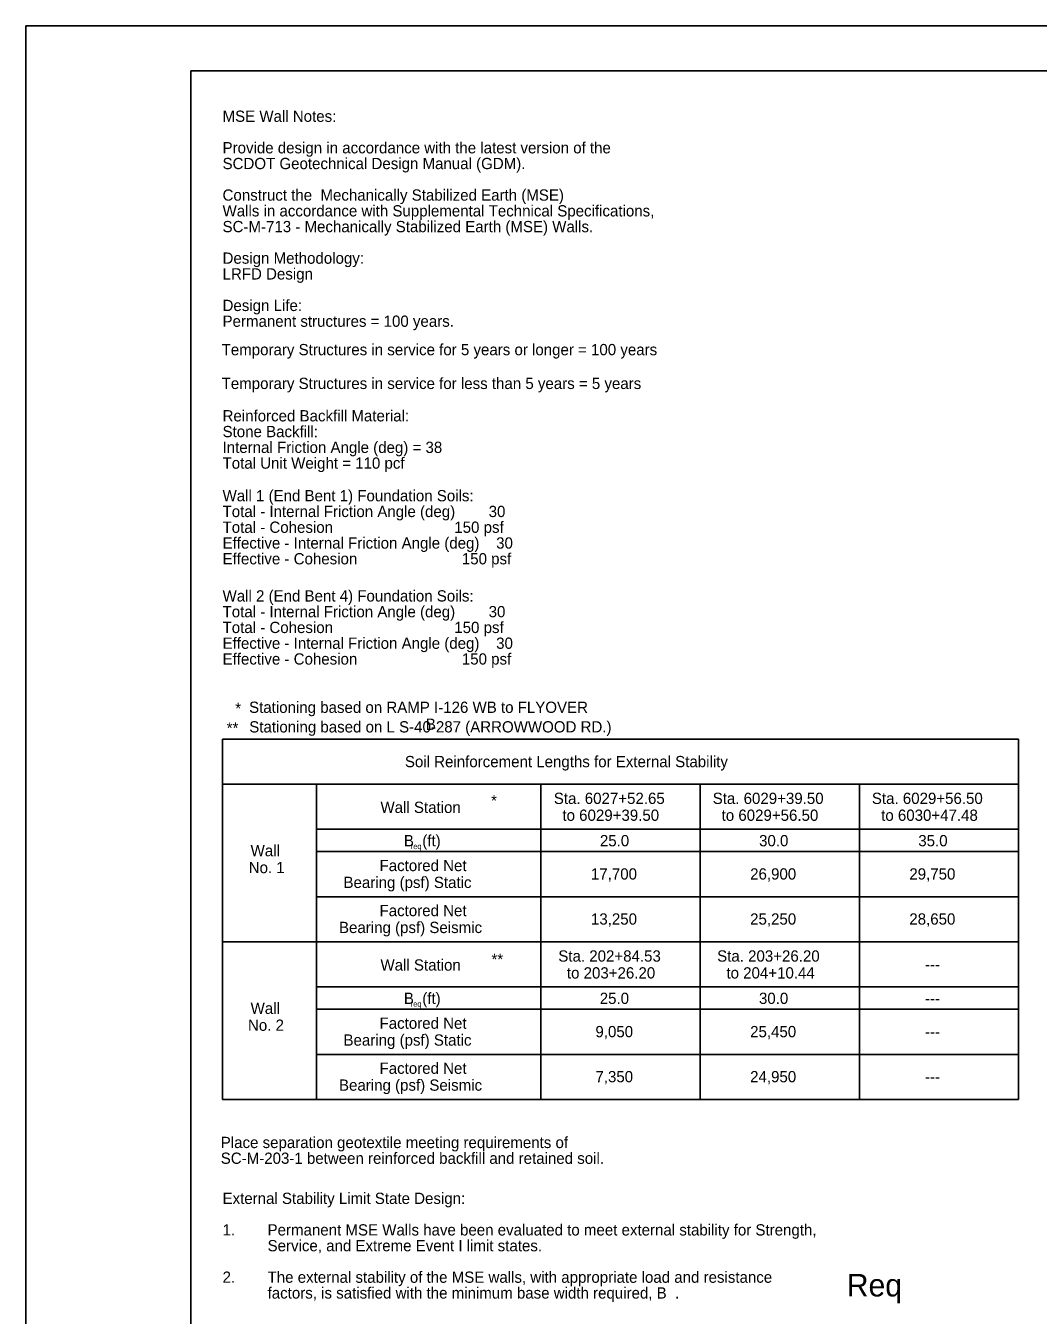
# Model space of a CAD drawing. Extents: x 96 to 240, y 601 to 689.
# Drawn here: x 95.8 to 140.8, y 631.8 to 689 of the extents above; entities that cross this region are included whole.
import ezdxf

# ---------------------------------------------------------------- set-up
doc = ezdxf.new("R2010")
doc.units = 0
for name, color, linetype in [('BR_BORDER LINES', 7, 'Continuous'), ('BR_TABLE LINES', 7, 'Continuous'), ('BR_TEXT', 7, 'Continuous'), ('Level 31', 7, 'Continuous')]:
    doc.layers.add(name, color=color, linetype=linetype)

msp = doc.modelspace()

# ---------------------------------------------------------------- linework, layer by layer
at = {"layer": 'BR_BORDER LINES'}
for p in [(237.837, 687.003), (103.173, 603.003)]:
    msp.add_line(p, (103.173, 687.003), dxfattribs=at)
at = {"layer": 'BR_TABLE LINES'}
for p, q in [((139.93, 657.337), (104.579, 657.337)), ((104.579, 657.337), (104.579, 641.337)), ((139.93, 657.337), (139.93, 641.337)), ((139.93, 655.337), (104.579, 655.337)), ((108.755, 655.337), (108.755, 641.337)), ((118.72, 655.337), (118.72, 641.337)), ((125.79, 655.337), (125.79, 641.337)), ((132.86, 655.337), (132.86, 641.337)), ((139.93, 653.337), (108.755, 653.337)), ((139.93, 652.337), (108.755, 652.337)), ((139.93, 650.337), (108.755, 650.337)), ((139.93, 648.337), (104.579, 648.337)), ((139.93, 646.337), (108.755, 646.337)), ((139.93, 645.337), (108.755, 645.337)), ((139.93, 643.337), (108.755, 643.337)), ((139.93, 641.337), (104.579, 641.337))]:
    msp.add_line(p, q, dxfattribs=at)
at = {"layer": 'Level 31'}
msp.add_line((239.84, 689.004), (95.84, 689.004), dxfattribs=at)
msp.add_lwpolyline([(95.84, 689.004), (95.84, 601.004), (239.84, 601.004), (239.84, 689.004)], dxfattribs=at)

# ---------------------------------------------------------------- texts
at = {"layer": 'BR_TEXT'}
for s, height, p in [('MSE Wall Notes:', 0.5, (104.579, 684.739)), ('Provide design in accordance with the latest version of the ', 0.5, (104.579, 683.339)), ('SCDOT Geotechnical Design Manual (GDM). ', 0.5, (104.579, 682.639)), ('Construct the  Mechanically Stabilized Earth (MSE) ', 0.5, (104.579, 681.239)), ('Walls in accordance with Supplemental Technical Specifications,', 0.5, (104.579, 680.539)), ('SC-M-713 - Mechanically Stabilized Earth (MSE) Walls.', 0.5, (104.579, 679.839)), ('Design Methodology:', 0.5, (104.579, 678.439)), ('LRFD Design', 0.5, (104.579, 677.739)), ('Design Life:', 0.5, (104.579, 676.339)), ('Permanent structures = 100 years.', 0.5, (104.579, 675.639)), ('Temporary Structures in service for 5 years or longer = 100 years ', 0.5, (104.538, 674.377)), ('Temporary Structures in service for less than 5 years = 5 years ', 0.5, (104.538, 672.877)), ('Reinforced Backfill Material:', 0.5, (104.579, 671.439)), ('Stone Backfill:', 0.5, (104.579, 670.739)), ('Internal Friction Angle (deg) = 38', 0.5, (104.579, 670.039)), ('Total Unit Weight = 110 pcf', 0.5, (104.579, 669.339)), ('Wall 1 (End Bent 1) Foundation Soils:', 0.5, (104.579, 667.892)), ('Total - Internal Friction Angle (deg)        30', 0.5, (104.579, 667.192)), ('Total - Cohesion                             150 psf', 0.5, (104.579, 666.492)), ('Effective - Internal Friction Angle (deg)    30', 0.5, (104.579, 665.792)), ('Effective - Cohesion                         150 psf', 0.5, (104.579, 665.092)), ('Wall 2 (End Bent 4) Foundation Soils:', 0.5, (104.579, 663.443)), ('Total - Internal Friction Angle (deg)        30', 0.5, (104.579, 662.743)), ('Total - Cohesion                             150 psf', 0.5, (104.579, 662.043)), ('Effective - Internal Friction Angle (deg)    30', 0.5, (104.579, 661.343)), ('Effective - Cohesion                         150 psf', 0.5, (104.579, 660.643)), ('Stationing based on RAMP I-126 WB to FLYOVER', 0.5, (105.757, 658.498)), ('Stationing based on L S-40-287 (ARROWWOOD RD.)', 0.5, (105.764, 657.629)), ('B', 0.5, (113.607, 657.745)), ('Place separation geotextile meeting requirements of ', 0.5, (104.499, 639.177)), ('SC-M-203-1 between reinforced backfill and retained soil.', 0.5, (104.499, 638.477)), ('External Stability Limit State Design:', 0.5, (104.579, 636.696)), ('1.', 0.5, (104.579, 635.296)), ('Permanent MSE Walls have been evaluated to meet external stability for Strength,', 0.5, (106.579, 635.296)), ('Service, and Extreme Event I limit states.', 0.5, (106.579, 634.596)), ('2.', 0.5, (104.579, 633.196)), ('The external stability of the MSE walls, with appropriate load and resistance', 0.5, (106.579, 633.196)), ('          Req', 1, (128.587, 632.59)), ('factors, is satisfied with the minimum base width required, B  .', 0.5, (106.579, 632.496))]:
    msp.add_text(s, height=height, dxfattribs=at).set_placement(p)
for s, height, p in [('*', 0.5, (105.143, 658.445)), ('**', 0.5, (104.764, 657.577)), ('Soil Reinforcement Lengths for External Stability', 0.5, (112.677, 656.087)), ('Sta. 6027+52.65 ', 0.5, (119.291, 654.455)), ('Sta. 6029+39.50', 0.5, (126.346, 654.455)), ('Sta. 6029+56.50', 0.5, (133.416, 654.455)), ('Wall Station', 0.5, (111.592, 654.056)), ('*', 0.5, (116.504, 654.355)), ('to 6029+39.50', 0.5, (119.673, 653.705)), ('to 6029+56.50', 0.5, (126.743, 653.705)), ('to 6030+47.48', 0.5, (133.829, 653.705)), ('Wall', 0.5, (105.824, 652.134)), ('B  (ft)', 0.5, (112.631, 652.576)), ('req', 0.25, (112.933, 652.45)), ('25.0', 0.5, (121.337, 652.576)), ('30.0', 0.5, (128.407, 652.576)), ('35.0', 0.5, (135.477, 652.576)), ('No. 1', 0.5, (105.741, 651.384)), ('Factored Net', 0.5, (111.551, 651.473)), ('17,700', 0.5, (120.94, 651.098)), ('26,900', 0.5, (128.01, 651.098)), ('29,750', 0.5, (135.08, 651.098)), ('Bearing (psf) Static', 0.5, (109.95, 650.723)), ('Factored Net', 0.5, (111.551, 649.473)), ('Bearing (psf) Seismic', 0.5, (109.75, 648.723)), ('13,250', 0.5, (120.94, 649.098)), ('25,250', 0.5, (128.01, 649.098)), ('28,650', 0.5, (135.08, 649.098)), ('Wall Station', 0.5, (111.592, 647.056)), ('**', 0.5, (116.521, 647.307)), ('Sta. 202+84.53 ', 0.5, (119.49, 647.455)), ('Sta. 203+26.20', 0.5, (126.544, 647.455)), ('to 203+26.20', 0.5, (119.871, 646.705)), ('to 204+10.44', 0.5, (126.957, 646.705)), ('---', 0.5, (135.78, 647.08)), ('B  (ft)', 0.5, (112.631, 645.576)), ('25.0', 0.5, (121.331, 645.576)), ('30.0', 0.5, (128.401, 645.576)), ('---', 0.5, (135.78, 645.576)), ('Wall', 0.5, (105.824, 645.134)), ('req', 0.25, (112.933, 645.45)), ('No. 2', 0.5, (105.707, 644.384)), ('Factored Net', 0.5, (111.551, 644.473)), ('9,050', 0.5, (121.138, 644.098)), ('25,450', 0.5, (128.01, 644.098)), ('Bearing (psf) Static', 0.5, (109.95, 643.723)), ('---', 0.5, (135.78, 644.098)), ('Factored Net', 0.5, (111.551, 642.473)), ('7,350', 0.5, (121.138, 642.098)), ('24,950', 0.5, (128.01, 642.098)), ('---', 0.5, (135.78, 642.098)), ('Bearing (psf) Seismic', 0.5, (109.75, 641.723))]:
    msp.add_text(s, height=height, rotation=359.9999, dxfattribs=at).set_placement(p)

doc.saveas('drawing.dxf')
